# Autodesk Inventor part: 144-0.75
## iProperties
Created: 2007-06
Part Number: 144-0.75
Document SubType Name: Modeling
Designer: btaylor
Density: 1 g/cm^3
Author: btaylor
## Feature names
1. Extrusion1
2. Extrusion2
3. Extrusion3
4. Hole1
5. Revolution2
6. Revolution3
7. Fillet1
8. Fillet2
9. Chamfer3
10. Chamfer4
11. Chamfer5
12. Chamfer6
